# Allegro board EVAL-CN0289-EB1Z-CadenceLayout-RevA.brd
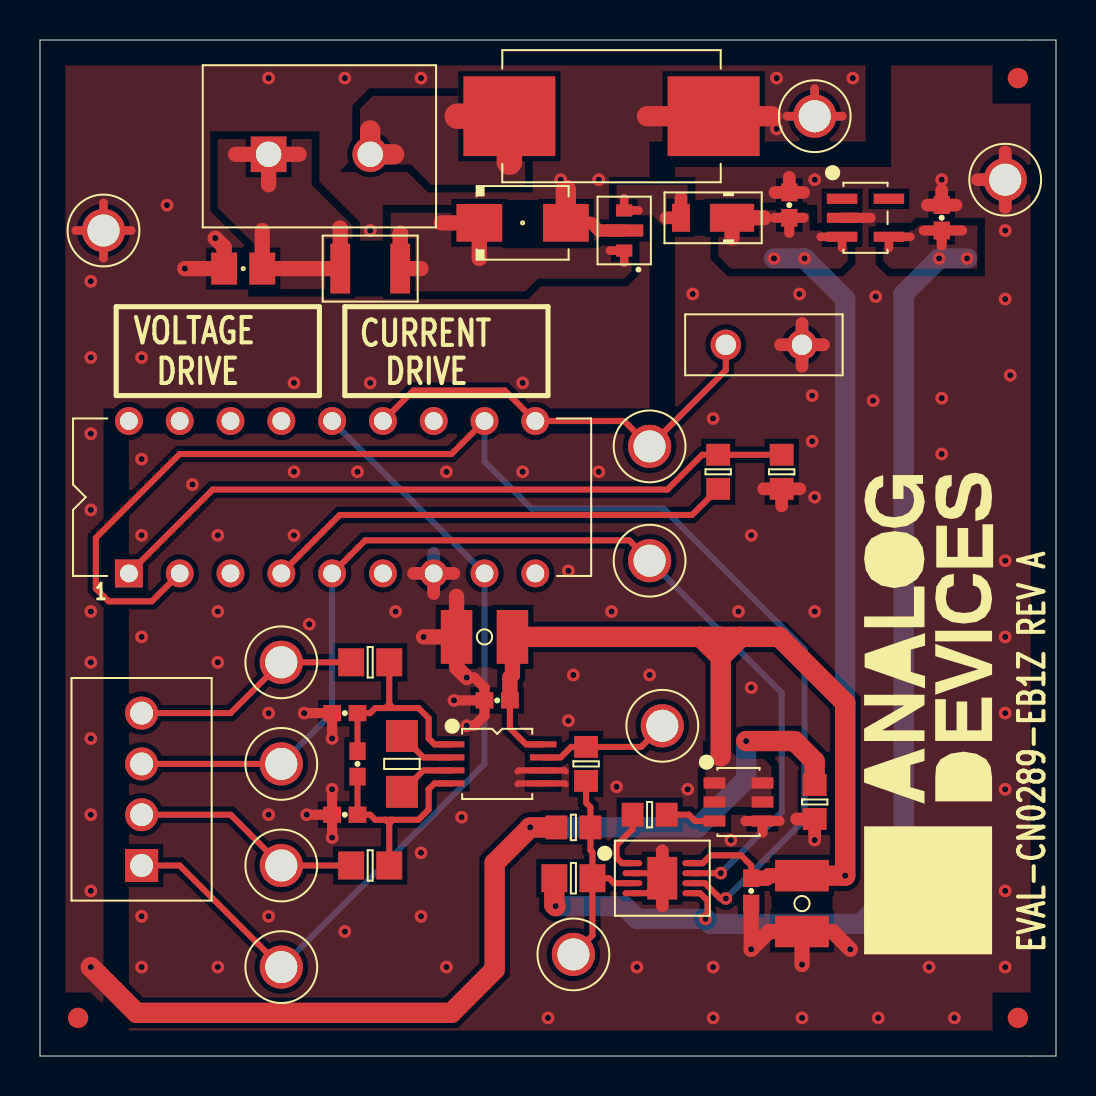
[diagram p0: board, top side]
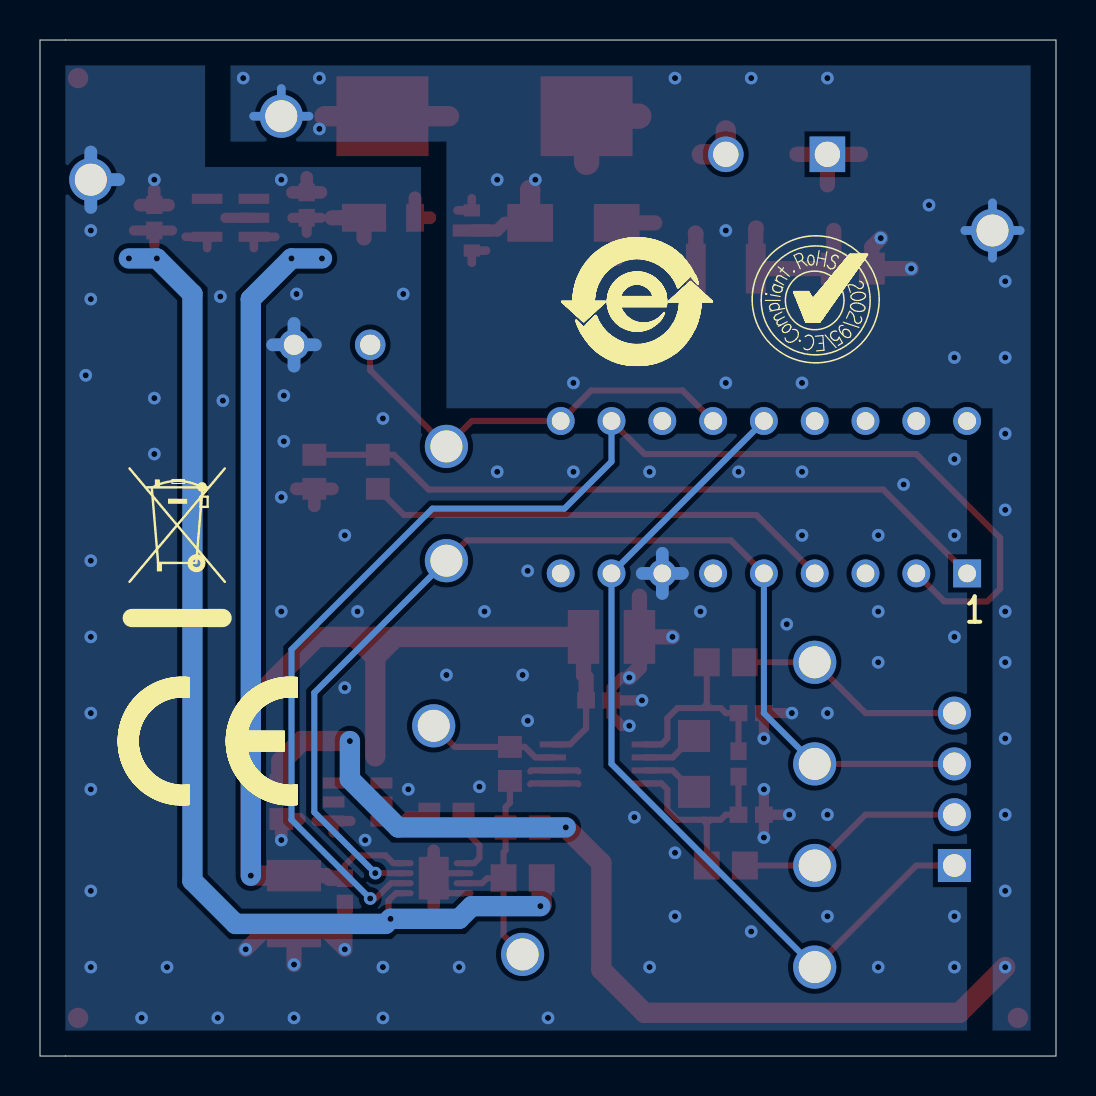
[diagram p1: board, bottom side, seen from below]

Outline 50.8 x 50.8 mm; copper layers: TOP, BOTTOM. Coordinates in mm from the lower left corner of the outline.
Outline path: 0,50.8 50.8,50.8 50.8,0 0,0 0,50.8

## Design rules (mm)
nets with their own width: min track width 0.508; nets AGND

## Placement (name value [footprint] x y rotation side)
C1  1000pF  [C0402]  15.24 17.14 180 top
C2  1000pF  [C0402]  15.24 12.06 0 top
C3  10000pF  [C0402]  15.88 14.6 270 top
C4  10uF  [C1210]  22.23 20.96 0 top
C5  1000pF  [C0402]  22.86 17.78 0 top
C6  10uF  [C1210]  38.1 7.62 90 top
C7  1000pF  [C0402]  35.56 8.25 90 top
C8  1000pF  [C0402]  37.47 42.55 270 top
C9  1000pF  [C0402]  45.09 41.91 270 top
C10  4.7UF  [C0805]  10.16 39.37 0 top
D1  SMAZ36-TP  [DIOSMJ5_0]  24.13 41.66 0 top
D2  SBR2U30P1-7  [POWERDI123]  33.66 41.91 180 top
F1  0.20A  [F1210]  16.51 39.37 0 top
FL1  0.1uF  [FSM0805L79W49H34]  29.21 41.27 90 top
GND  K24A W. EYELET T15.23  [CNLOOPTP]  48.26 43.81 0 top
GNDSNS  K24A W. EYELET T15.23  [CNLOOPTP]  12.06 4.45 0 top
J1  282834-4  [CN1X4H406]  5.08 9.53 90 top
J2  OSTTC022162  [CN1X2H406]  11.43 45.09 0 top
LOOPGND  K24A W. EYELET T15.23  [CNLOOPTP]  3.17 41.27 0 top
NOREF  -  []  -132.72 -239.08 0 top
NOREF#2  -  [unnamed#2]  1.91 1.91 0 top
NOREF#3  -  []  76.2 0 90 top
NOREF#4  -  []  1.91 1.91 0 top
NOREF#5  -  []  -30.8 140.02 0 top
NOREF#6  -  []  -15.88 -47.12 0 top
NOREF#7  -  []  0 0 0 top
NOREF#8  -  []  -132.72 -239.08 0 top
NOREF#9  -  []  0 50.8 0 top
NOREF#10  -  []  50.8 0 0 top
NOREF#11  -  []  0 50.8 0 top
NOREF#12  -  []  -132.72 -239.08 0 top
NOREF#13  -  []  0 0 0 top
NOREF#14  -  [unnamed#2]  48.9 1.91 0 top
NOREF#15  -  []  50.8 0 90 top
NOREF#16  -  []  24.64 73.91 0 top
NOREF#17  -  []  50.8 50.8 180 top
NOREF#18  -  []  1.91 1.91 0 top
NOREF#19  -  []  44.45 17.78 90 top
NOREF#20  -  []  0 0 0 top
NOREF#21  -  []  0 50.8 270 top
NOREF#22  -  [unnamed#2]  48.9 48.9 0 top
NOREF#23  -  []  12.06 37.72 180 bottom
NOREF#24  -  []  43.94 26.54 180 bottom
NOREF#25  -  []  20.96 37.72 180 bottom
NOREF#26  -  []  40.89 15.75 180 bottom
Q1  HMC313E  [SOT26-2]  34.93 12.7 270 top
R1  4.02K  [R0805]  16.51 19.69 0 top
R2  4.02K  [R0805]  16.51 9.53 0 top
R3  1K  [R1206]  18.1 14.6 90 top
R4  2.5K  [RCK02]  38.1 35.56 180 top
R5  10K  [R0603]  33.91 29.21 90 top
R6  10K  [R0603]  37.08 29.21 90 top
R7  250  [R4124]  28.58 46.99 0 top
R8  10  [R0603]  38.73 12.7 270 top
R9  30K  [R0603]  27.3 14.6 270 top
R10  1K  [R0603]  26.67 11.43 0 top
R11  30K  [R0603]  30.48 12.06 0 top
R12  130K  [R0805]  26.67 8.89 180 top
S1  ASE6204  [SWDIP18]  4.45 24.13 0 top
SUPPLYSNS  K24A W. EYELET T15.23  [CNLOOPTP]  12.06 14.6 0 top
TP1  K24A W. EYELET T15.23  [CNLOOPTP]  38.73 46.99 0 top
TP2  K24A W. EYELET T15.23  [CNLOOPTP]  30.48 24.77 0 top
TP3  K24A W. EYELET T15.23  [CNLOOPTP]  30.48 30.48 0 top
TP4  K24A W. EYELET T15.23  [CNLOOPTP]  31.12 16.51 0 top
TP5  K24A W. EYELET T15.23  [CNLOOPTP]  26.67 5.08 0 top
U1  AD8226BRMZ  [MSOP8]  22.86 14.6 270 top
U2  ADA4091-2ACPZ  [QFN8_3X3_PAD2_13X1_5]  31.12 8.89 270 top
U3  ADR02BUJZ  [TSOT-5]  41.27 41.91 270 top
UNK+V  K24A W. EYELET T15.23  [CNLOOPTP]  12.06 9.53 0 top
UNK-V  K24A W. EYELET T15.23  [CNLOOPTP]  12.06 19.69 0 top

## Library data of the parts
C1 C2 C5 C7-C9 = CAP: Tolerance: 5; User Part Number: UPN; alternate symbols: (C0402H22_ALT,C0201-2); part number: CAP_SM-1000PF,50V,5,E012419,C0402; tolerance: 5
C3 = CAP: Tolerance: 10; User Part Number: UPN; alternate symbols: (C0402H22_ALT,C0201-2); part number: CAP_SM-10000PF,25V,10,E013688,C0402; tolerance: 10
C4 C6 = CAP: Tolerance: 10; User Part Number: UPN; alternate symbols: (C0402H22_ALT,C0201-2); part number: CAP_SM-10UF,25V,10,E011786,C1210; tolerance: 10
C10 = CAP: Tolerance: 10; User Part Number: UPN; alternate symbols: (C0402H22_ALT,C0201-2); part number: CAP_SM-4.7UF,25V,10,E006908,C0805; tolerance: 10
D1 = DIOZNR: Tolerance: 5; User Part Number: UPN; part number: DIOZNR_SM-SMAZ36-TP,36V,5,E017811,DIOSMJ5_0; tolerance: 5
D2 = DIO: User Part Number: UPN; Tolerance: N/A; part number: DIO_SM-SBR2U30P1-7,30V,N/A,E016912,POWERDI123; tolerance: N/A
F1 = FSFUSE: User Part Number: UPN; part number: FSFUSE_SM-0.20A,30V,E016947,F1210
FL1 = FLTR3P: Tolerance: 20; User Part Number: UPN; part number: FLTR3P_SM-0.1UF,E010964,FSM0805L79W49H34; tolerance: 20
GND GNDSNS LOOPGND SUPPLYSNS TP1-TP5 UNK+V UNK-V = CNTP1P: User Part Number: UPN; part number: CNTP1P_TH-K24A W. EYELET T15.23,E005673,CNLOOPTP
J1 = CN4P: User Part Number: UPN; part number: CN4P_TH-282834-4,E016935,CN1X4H406
J2 = CN2P: User Part Number: UPN; part number: CN2P_TH-OSTTC022162,E016936,CN1X2H406
Q1 = ICHMC313: User Part Number: UPN; part number: ICHMC313_SM-HMC313E,E010134,SOT26-2
R1 R2 = RES: Tolerance: 1; User Part Number: UPN; alternate symbols: (RRAD984L1500W75H520LD32); part number: RES_SM-4.02K,1/8W,1,E003522,R0805; tolerance: 1
R3 = RES: Tolerance: 0.05; User Part Number: UPN; alternate symbols: (RRAD984L1500W75H520LD32); part number: RES_SM-1K,1/4W,0.05,E004440,R1206; tolerance: 0.05
R4 = RES: Tolerance: 0.005; User Part Number: UPN; alternate symbols: (RRAD984L1500W75H520LD32;TO220H590_ALT); part number: RES_TH-2.5K,0.6W,0.005,E017769,RCK02; tolerance: 0.005
R5 R6 = RES: Tolerance: 1; User Part Number: UPN; alternate symbols: (RRAD984L1500W75H520LD32); part number: RES_SM-10K,1/10W,1,E003671,R0603; tolerance: 1
R7 = RES: Tolerance: 1; User Part Number: UPN; alternate symbols: (RRAD984L1500W75H520LD32); part number: RES_SM-250,2W,1,E017807,R4124; tolerance: 1
R8 = RES: Tolerance: 1; User Part Number: UPN; alternate symbols: (RRAD984L1500W75H520LD32); part number: RES_SM-10,1/10W,1,E003666,R0603; tolerance: 1
R9 R11 = RES: Tolerance: 0.1; User Part Number: UPN; alternate symbols: (RRAD984L1500W75H520LD32); part number: RES_SM-30K,1/10W,0.1,E003958,R0603; tolerance: 0.1
R10 = RES: Tolerance: 0.1; User Part Number: UPN; alternate symbols: (RRAD984L1500W75H520LD32); part number: RES_SM-1K,1/10W,0.1,E010662,R0603; tolerance: 0.1
R12 = RES: Tolerance: 1; User Part Number: UPN; alternate symbols: (RRAD984L1500W75H520LD32); part number: RES_SM-130K,1/8W,1,E003566,R0805; tolerance: 1
S1 = SW6PDT: User Part Number: UPN; part number: SW6PDT_TH-ASE6204,E016934,SWDIP18
U1 = AD8220: User Part Number: UPN; part number: AD8220_SM-AD8226BRMZ,E013818,MSOP8,N/A
U2 = ADA4091_2: User Part Number: UPN; part number: ADA4091_2_SM-ADA4091-2ACPZ,E016852,QFN8_3X3_PAD2_13X1_5,N/A
U3 = ADR0X: User Part Number: UPN; part number: ADR0X_SM-ADR02BUJZ,E016933,TSOT-5,N/A

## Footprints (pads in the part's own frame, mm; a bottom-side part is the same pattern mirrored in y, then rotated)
C0402
  rect 0.889x0.813 smd: 1(-0.635,0) 2(0.635,0)
C0805
  rect 1.295x1.6 smd: 1(-0.953,0) 2(0.953,0)
C1210
  rect 1.575x2.692 smd: 1(-1.397,0) 2(1.397,0)
CN1X2H406
  rect 1.778x1.778 hole 1.27: 1(0,0)
  round 1.778 hole 1.27: 2(5.08,0)
CN1X4H406
  rect 1.651x1.651 hole 1.143: 1(0,0)
  round 1.651 hole 1.143: 2(2.54,0) 3(5.08,0) 4(7.62,0)
CNLOOPTP
  round 2.159 hole 1.6: 1(0,0)
DIOSMJ5_0
  rect 2.286x1.88 smd: A(2.164,0) C(-2.164,0)
F1210
  rect 0.991x2.489 smd: 1(-1.499,0) 2(1.499,0)
FSM0805L79W49H34
  rect 0.61x0.813 smd: 1(-1.005,0) 3(1.005,0)
  rect 0.61x1.905 smd: 2(0,0)
MSOP8
  rect 0.305x1.321 smd: 1(-0.975,-2.3) 2(-0.325,-2.3) 3(0.325,-2.3) 4(0.975,-2.3) 5(0.975,2.3) 6(0.325,2.3) 7(-0.325,2.3) 8(-0.975,2.3)
POWERDI123
  rect 0.889x1.397 smd: A(1.606,0)
  rect 2.21x1.397 smd: C(-0.945,0)
QFN8_3X3_PAD2_13X1_5
  oval 0.305x0.991 smd: 1(-0.75,-1.495) 2(-0.25,-1.495) 3(0.25,-1.495) 4(0.75,-1.495) 5(0.75,1.495) 6(0.25,1.495) 7(-0.25,1.495) 8(-0.75,1.495)
  rect 2.134x1.499 smd: PAD(0,0)
R0603
  rect 1.092x1.194 smd: 1(-0.851,0) 2(0.851,0)
R0805
  rect 1.295x1.397 smd: 1(-0.953,0) 2(0.953,0)
R1206
  rect 1.6x1.6 smd: 1(-1.397,0) 2(1.397,0)
R4124
  rect 4.597x3.988 smd: 1(-5.105,0) 2(5.105,0)
RCK02
  round 1.524 hole 1.016: 1(0,0) 2(3.81,0)
SOT26-2
  rect 0.559x1.092 smd: 1(-0.95,-1.2) 2(0,-1.2) 3(0.95,-1.2) 4(0.95,1.2) 5(0,1.2) 6(-0.95,1.2)
SWDIP18
  rect 1.397x1.397 hole 0.889: 1(0,0)
  round 1.397 hole 0.889: 2(2.54,0) 3(5.08,0) 4(7.62,0) 5(10.16,0) 6(12.7,0) 7(15.24,0) 8(17.78,0) 9(20.32,0) 10(20.32,7.62) 11(17.78,7.62) 12(15.24,7.62) 13(12.7,7.62) 14(10.16,7.62) 15(7.62,7.62) 16(5.08,7.62) 17(2.54,7.62) 18(0,7.62)
TSOT-5
  rect 0.508x1.524 smd: 1(-0.95,-1.17) 2(0,-1.17) 3(0.95,-1.17) 4(0.95,1.17) 5(-0.95,1.17)
unnamed#2
  round 1.016 smd: (0,0)

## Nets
+5V: C9.2(N2) R12.2(N2) U2.5(+IN) U3.4(VOUT)
+VCC: C4.2(N2) C5.2(N2) C6.2(N2) C7.2(N2) C8.2(N2) D2.C(N) Q1.1(OUT) Q1.2(GND2) Q1.5(GND5) Q1.6(GND6) U1.8(VS+) U2.8(+V) U3.3(VIN)
AGND: C1.2(N2) C2.1(N1) C4.1(N1) C5.1(N1) C6.1(N1) C7.1(N1) C8.1(N1) C9.1(N1) GND.1(N1) Q1.4(GND4) R4.1(N1) R6.1(N1) R8.2(N2) S1.7(NC3) U1.5(VS-) U1.6(REF) U2.2(-IN) U2.4(-V) U2.PAD(-V1) U3.2(GND)
DGND: C10.1(N1) D1.A(P) FL1.2(GND) LOOPGND.1(N1) R7.2(N2) R8.1(N1) R10.1(N1) TP1.1(N1)
+V_SENSOR_OUTPUT: J1.2(N2) R2.1(N1) UNK+V.1
-V_SENSOR_OUTPUT: J1.4(N4) R1.1(N1) UNK-V.1
OUTA: R11.1(N1) U2.1(OUT)
SENSOR_GND: GNDSNS.1(N1) J1.1(N1) S1.8(C3) S1.14(C5)
SENSOR_SUPPLY: J1.3(N3) S1.5(C2) SUPPLYSNS.1(N1) TP2.1(N1) U2.7(OUT)
UNNAMED_2_AD8220_I94_IN: C1.1(N1) C3.1(N1) R1.2(N2) U1.1(IN-)
UNNAMED_2_AD8220_I94_IN_1: C2.2(N2) C3.2(N2) R2.2(N2) U1.4(IN+)
UNNAMED_2_AD8220_I94_OUT: R9.1(N1) TP4.1(N1) U1.7(OUT)
UNNAMED_2_AD8220_I94_RG: R3.2(N2) U1.2(RG)
UNNAMED_2_AD8220_I94_RG1: R3.1(N1) U1.3(RG1)
UNNAMED_2_ADA40912_I91__1: R9.2(N2) R10.2(N2) R12.1(N1) TP5.1(N1) U2.3(+IN)
UNNAMED_2_ADA40912_I92_: S1.2(C1) S1.11(C4) U2.6(-IN)
UNNAMED_2_CAP_I98_N2: C10.2(N2) F1.1(N1) J2.1(N1)
UNNAMED_2_CN2P_I187_N2: J2.2(N2) R7.1(N1)
UNNAMED_2_CNTP1P_I152_N1: R4.2(N2) S1.10(NO4) S1.13(NO5) TP3.1(N1)
UNNAMED_2_DIO_I100_P: D2.A(P) FL1.3(OUT)
UNNAMED_2_FLTR3P_I123_IN: D1.C(N) F1.2(N2) FL1.1(IN)
UNNAMED_2_RES_I113_N1: R5.1(N1) S1.4(NC2)
UNNAMED_2_RES_I113_N2: R5.2(N2) R6.2(N2) S1.1(NC1)
UNNAMED_2_RES_I159_N2: Q1.3(IN) R11.2(N2)

Pads without a net: S1 3 6 9 12 15 16 17 18; U3 1 5

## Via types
v1: diameter 0.635, hole 0.305, TOP to BOTTOM, 117 vias

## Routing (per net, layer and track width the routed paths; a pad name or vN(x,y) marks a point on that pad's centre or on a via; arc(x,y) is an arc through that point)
+5V: length 59.5
  TOP w0.305: v1(33.27,6.86) 33.38,6.96 33.38,7.77 33.01,8.14 U2.5
  TOP w0.432: 42.44,40.4 U3.4 43.51,40.96
  TOP w0.508: 46.1,41.27 C9.2 ; C9.2 45.09,40.53 ; C9.2 44.2,41.27
  TOP w1.016: R12.2 25.72,7.56 v1(25.78,7.49)
  BOTTOM w1.016: v1(25.78,7.49) 29.21,7.49 29.85,6.86 v1(33.27,6.86) 33.53,6.6 41.02,6.6 43.18,8.76 43.18,38.1 v1(44.96,39.88) v1(46.36,39.88)
+VCC: length 90.4
  TOP w0.305: C7.2 35.56,9.53 35.05,10.03 33.53,10.03 33.14,9.64 U2.8 ; U1.8 24.3,15.58 23.5,16.38 C5.2
  TOP w0.432: 40.11,40.4 U3.3 39.04,40.96
  TOP w0.508: C8.2 36.75,41.91 ; C8.2 37.47,41.16 ; C8.2 38.18,41.91
  TOP w0.762: C7.2 36.32,8.89 36.45,9.02 C6.2 ; 36.2,41.91 D2.C 34.6,40.91 ; C4.2 23.62,19.05 23.5,18.92 C5.2
  TOP w1.016: 34.04,19.94 35.05,20.96 ; 34.04,19.94 34.04,20.96 ; 34.04,19.94 34.04,14.99 ; 34.04,19.94 33.02,20.96 ; 35.05,20.96 36.96,20.96 40.26,17.65 v1(40.26,9.02) C6.2 ; 35.05,20.96 34.04,20.96 ; 34.04,20.96 33.02,20.96 ; 33.02,20.96 C4.2
  BOTTOM w1.016: v1(36.7,39.88) v1(38.23,39.88) 40.26,37.85 v1(40.26,9.02)
AGND: length 74.4
  TOP w0.305: 26.29,14.22 26.23,14.28 U1.6 23.93,14.28 23.88,14.22 ; 23.88,13.59 23.92,13.63 U1.5 26.25,13.63 26.29,13.59 ; U2.2 30.87,9.14 U2.PAD 30.36,8.14 U2.4
  TOP w0.508: C5.1 22.23,17.02 21.72,16.51 v1(21.34,16.51) ; C5.1 v1(20.7,17.78) ; C5.1 22.23,18.42 21.72,18.92 v1(21.34,18.92) ; C2.1 v1(14.6,13.33) ; C2.1 v1(13.33,12.06) ; C2.1 v1(14.6,10.92) ; v1(13.21,17.14) C1.2 v1(14.6,15.88) ; 36.12,11.17 Q1.4 ; Q1.4 35.27,11.75 ; Q1.4 36.98,11.75 ; U3.2 41.53,41.91
  TOP w0.635: S1.7 20.69,24.13 ; S1.7 19.69,23.13 ; S1.7 18.68,24.13 ; GND.1 48.26,45.2 ; GND.1 46.88,43.81 ; GND.1 48.26,42.43 ; 31.12,7.52 U2.PAD 31.12,10.26 ; C9.1 45.09,43.29 ; C9.1 44.37,42.55 ; C9.1 45.8,42.55 ; R4.1 39.17,35.56 ; R4.1 38.1,34.49 ; R4.1 37.03,35.56 ; R4.1 38.1,36.63 ; 36.18,28.36 R6.1 ; R6.1 37.99,28.36 ; R6.1 37.08,27.51 ; C8.1 38.18,43.18 ; C8.1 37.47,43.93 ; C8.1 36.75,43.18 ; 38.73,11 R8.2 37.83,11.85
  TOP w0.762: C4.1 20.83,22.99 ; C4.1 v1(19.18,20.96) ; C4.1 20.83,19.43 v1(21.34,18.92) ; C7.1 v1(35.56,5.33) 36.45,6.22 C6.1 ; C6.1 39.62,6.22 v1(40.51,5.33) ; C6.1 v1(38.1,4.57)
  BOTTOM w0.635: 37.03,35.56 R4.1 ; R4.1 38.1,36.63 ; R4.1 38.1,34.49 ; R4.1 39.17,35.56 ; 18.68,24.13 S1.7 ; S1.7 20.69,24.13 ; S1.7 19.69,25.13 ; S1.7 19.69,23.13 ; 46.88,43.81 GND.1 ; GND.1 48.26,45.2 ; GND.1 48.26,42.43
  vias: v1(5.08,29.85) v1(5.08,26.04) v1(5.08,20.96) v1(5.08,6.99) v1(5.08,4.45) v1(7.62,28.58) v1(8.89,26.04) v1(8.89,22.23) v1(8.89,19.69) v1(8.89,4.45) v1(11.43,17.14) v1(11.43,12.06) v1(11.43,6.99) v1(12.7,29.21) v1(12.7,26.04) v1(13.46,21.59) v1(15.24,6.22) v1(15.88,29.21) v1(17.78,22.23) v1(19.05,10.16) v1(19.05,6.99) v1(20.32,29.21) v1(20.32,4.45) v1(21.08,11.94) v1(24.13,29.21) v1(25.4,1.91) v1(26.42,24.26) v1(26.42,16.76) v1(26.67,19.05) v1(27.94,29.21) v1(28.58,22.23) v1(28.83,13.46) v1(29.85,4.45) v1(30.48,19.05) v1(32.38,13.33) v1(32.64,38.1) v1(33.66,31.88) v1(33.66,4.45) v1(33.66,1.91) v1(34.54,10.79) v1(34.93,22.23) v1(35.56,26.04) v1(35.56,18.42) v1(37.97,38.1) v1(38.1,1.91) v1(38.61,33.02) v1(38.61,30.73) v1(38.73,43.81) v1(38.73,27.94) v1(38.73,22.23) v1(38.73,10.79) v1(41.66,32.77) v1(41.78,37.97) v1(41.91,1.91) v1(44.45,4.45) v1(45.09,43.81) v1(45.09,32.89) v1(45.09,30.1) v1(45.72,1.91) v1(48.26,41.27) v1(48.26,37.85) v1(48.26,24.77) v1(48.26,20.96) v1(48.26,17.14) v1(48.26,13.33) v1(48.26,8.25) v1(48.26,4.45) v1(48.51,34.04)
DGND: length 83.9
  TOP w0.432: LOOPGND.1 4.56,41.27 ; LOOPGND.1 3.17,42.66 ; LOOPGND.1 1.79,41.27 ; LOOPGND.1 3.17,39.89 ; TP1.1 38.73,48.37 ; TP1.1 37.35,46.99 ; TP1.1 40.12,46.99
  TOP w0.61: FL1.2 27.94,41.27 27.56,41.66 D1.A
  TOP w0.762: v1(7.24,39.37) C10.1 9.21,40.45 v1(8.76,40.89)
  TOP w1.016: 36.58,46.99 R7.2 30.35,46.99 ; v1(35.31,15.75) 37.72,15.75 38.73,14.73 R8.1 ; D1.A 26.29,43.3 26.29,43.31 ; R10.1 v1(24.51,11.43) 22.73,9.65 22.73,4.32 20.57,2.16 4.83,2.16 v1(2.54,4.45)
  BOTTOM w0.432: TP1.1 40.12,46.99 ; TP1.1 37.35,46.99 ; TP1.1 38.73,48.37 ; LOOPGND.1 3.17,42.66 ; LOOPGND.1 4.56,41.27 ; LOOPGND.1 1.79,41.27 ; LOOPGND.1 3.17,39.89
  BOTTOM w1.016: v1(24.51,11.43) 32.89,11.43 35.31,13.84 v1(35.31,15.75)
  vias: v1(2.54,38.73) v1(2.54,34.93) v1(2.54,31.12) v1(2.54,27.3) v1(2.54,22.23) v1(2.54,19.69) v1(2.54,15.88) v1(2.54,12.06) v1(2.54,8.25) v1(5.08,34.93) v1(6.35,42.55) v1(11.43,48.9) v1(12.7,33.66) v1(15.24,48.9) v1(16.51,41.27) v1(16.51,33.66) v1(19.05,48.9) v1(24.13,33.66) v1(26.04,43.81) v1(27.94,43.81) v1(36.83,48.9) v1(36.83,46.36) v1(40.64,48.9)
+V_SENSOR_OUTPUT: length 11.5
  TOP w0.305: J1.2 9.53,12.06 UNK+V.1 R2.1
-V_SENSOR_OUTPUT: length 11.5
  TOP w0.305: R1.1 UNK-V.1 9.53,17.14 J1.4
OUTA: length 3.4
  TOP w0.305: U2.1 29.09,9.64 28.83,9.91 28.83,10.54 29.63,11.34 R11.1
SENSOR_GND: length 43.8
  TOP w0.305: J1.1 6.99,9.53 GNDSNS.1
  BOTTOM w0.305: GNDSNS.1 22.23,14.6 S1.8 14.6,31.75
SENSOR_SUPPLY: length 55.6
  TOP w0.305: S1.5 16.26,25.78 29.46,25.78 TP2.1 ; U2.7 34.03,9.14 v1(34.04,9.14) ; J1.3 SUPPLYSNS.1
  BOTTOM w0.305: TP2.1 37.08,18.16 37.08,12.19 v1(34.04,9.14) ; SUPPLYSNS.1 14.6,17.14 S1.5
UNNAMED_2_AD8220_I94_IN: length 10.9
  TOP w0.305: 17.65,17.4 18.92,17.4 19.43,16.89 19.43,15.88 19.73,15.58 U1.1 ; 17.65,17.4 17.46,17.59 ; 17.65,17.4 17.53,17.4 ; 17.46,17.59 R1.2 ; 17.46,17.59 17.27,17.4 ; 17.46,17.59 17.46,17.46 17.53,17.4 ; 17.27,17.4 17.53,17.4 ; 17.27,17.4 16.76,17.4 16.51,17.14 C1.1 15.88,15.24
UNNAMED_2_AD8220_I94_IN_1: length 10.9
  TOP w0.305: 17.46,11.62 17.27,11.81 ; 17.46,11.62 R2.2 ; 17.46,11.62 17.46,11.75 17.53,11.81 ; 17.46,11.62 17.65,11.81 ; 17.27,11.81 17.53,11.81 ; 17.27,11.81 16.76,11.81 16.51,12.06 C2.2 C3.2 ; 17.53,11.81 17.65,11.81 ; U1.4 19.73,13.63 19.43,13.33 19.43,12.32 18.92,11.81 17.65,11.81
UNNAMED_2_AD8220_I94_OUT: length 6.6
  TOP w0.305: TP4.1 30.06,15.46 R9.1 26.56,15.46 26.04,14.93 U1.7
UNNAMED_2_AD8220_I94_RG: length 2.9
  TOP w0.305: U1.2 19.17,14.93 R3.2
UNNAMED_2_AD8220_I94_RG1: length 2.9
  TOP w0.305: 18.1,13.21 19.17,14.28 U1.3
UNNAMED_2_ADA40912_I91__1: length 11.3
  TOP w0.305: R12.1 28.45,8.89 28.7,8.64 U2.3 ; R12.1 27.62,6.03 TP5.1 ; R12.1 27.62,10.19 27.52,10.29 R10.2 27.52,12.45 27.3,12.66 R9.2
UNNAMED_2_ADA40912_I92_: length 67.4
  TOP w0.305: 22.23,31.75 20.57,30.1 6.99,30.1 2.79,25.91 2.79,23.37 3.43,22.73 5.59,22.73 S1.2 ; v1(34.29,7.87) 34.01,7.87 33.25,8.64 U2.6
  BOTTOM w0.305: 22.23,31.75 22.23,29.72 24.57,27.37 31.18,27.37 38.23,20.32 38.23,11.81 v1(34.29,7.87)
UNNAMED_2_CAP_I98_N2: length 12.5
  TOP w0.762: 9.78,45.09 J2.1 ; J2.1 12.95,45.09 ; J2.1 11.43,43.56 ; 11.11,41.27 C10.2 F1.1 15.01,41.38 14.99,41.4
UNNAMED_2_CN2P_I187_N2: length 7.3
  TOP w1.016: 17.7,45.09 J2.2 16.51,46.28
  TOP w1.27: 20.87,46.99 R7.1 23.47,44.69
UNNAMED_2_CNTP1P_I152_N1: length 21.8
  TOP w0.305: 17.14,31.75 18.67,33.27 23.24,33.27 24.77,31.75 29.21,31.75 TP3.1 34.29,34.29 R4.2
UNNAMED_2_DIO_I100_P: length 3.1
  TOP w0.432: 29.92,42.28 FL1.3 29.21,42.89
  TOP w0.635: 31.3,41.91 D2.A 32.05,42.91
UNNAMED_2_FLTR3P_I123_IN: length 7.8
  TOP w0.432: 29.21,39.66 FL1.1 28.5,40.27
  TOP w0.762: 21.97,39.88 21.97,39.88 D1.C 20.07,41.66 ; 18.03,41.15 18.01,41.12 F1.2 19.05,39.37
UNNAMED_2_RES_I113_N1: length 23.6
  TOP w0.305: S1.4 14.99,27.05 32.6,27.05 R5.1
UNNAMED_2_RES_I113_N2: length 35.1
  TOP w0.305: S1.1 8.64,28.32 31.37,28.32 33.11,30.06 R5.2 R6.2
UNNAMED_2_RES_I159_N2: length 2.5
  TOP w0.305: Q1.3 32.77,11.75 32.45,12.06 R11.2

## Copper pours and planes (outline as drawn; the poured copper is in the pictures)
+5V on TOP: 42.55,39.37 42.16,39.75 42.16,41.27 43.69,41.27 43.94,41.53 46.86,41.53 46.86,39.37
+VCC on TOP: 34.54,39.37 33.91,40.01 33.91,42.29 37.97,42.29 37.97,42.16 38.48,42.16 38.48,41.27 40.39,41.27 40.39,39.75 40.01,39.37
+VCC on TOP: 33.27,12.45 36.58,12.45 36.58,14.48 36.2,14.86 34.93,14.86 34.42,15.37 33.53,15.37 33.53,14.48 33.27,14.22
AGND on TOP: 4.45,1.27 4.45,31.12 31.75,31.12 31.75,44.45 42.55,44.45 42.55,49.53 47.62,49.53 47.62,47.62 49.53,47.62 49.53,3.17 47.62,3.17 47.62,1.27 ; 7 cut-outs
AGND on BOTTOM: 4.45,1.27 4.45,31.12 31.75,31.12 31.75,44.45 42.55,44.45 42.55,49.53 49.53,49.53 49.53,1.27
DGND on TOP: 3.17,2.54 2.54,3.17 1.27,3.17 1.27,49.53 30.48,49.53 41.27,49.53 41.27,45.72 30.48,45.72 30.48,32.38 3.17,32.38 ; 3 cut-outs
DGND on BOTTOM: 1.27,3.17 1.27,49.53 30.48,49.53 41.27,49.53 41.27,45.72 30.48,45.72 30.48,32.38 3.17,32.38 3.17,1.27 1.27,1.27 1.27,3.17
UNNAMED_2_CAP_I98_N2 on TOP: 8.89,45.85 13.59,45.85 13.59,43.56 15.62,41.53 15.62,38.35 10.79,38.35 10.79,40.51 8.89,42.42
UNNAMED_2_CN2P_I187_N2 on TOP: 15.88,44.58 18.54,44.58 19.56,43.56 24.26,43.56 24.26,48.01 16.64,48.01 16,47.37 16,44.7
UNNAMED_2_DIO_I100_P on TOP: 31.12,41.53 30.61,42.04 28.83,42.04 28.83,43.56 32.38,43.56 32.38,41.53
UNNAMED_2_FLTR3P_I123_IN on TOP: 17.53,38.23 17.53,42.16 23.11,42.16 23.11,40.39 27.94,40.39 28.07,40.51 29.59,40.51 29.59,39.24 29.21,38.86 24.89,38.86 24.26,38.23

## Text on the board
Ref Des/Silkscreen Top: VOLTAGE | DRIVE | CURRENT | EVAL-CN0289-EB1Z REV A
DIMENSION: REF
PAGE_OUTLINE: N/A | 24JUL12 | 10JAN13 | AD8226/ADA4091 CUSTOMER | EVALUATION BOARD | 20-035415
User.5: ROHS COMPLIANCE NOTE:  (Required for Customer Boards) Add to top of MATERIALS | 100 MICRO INCHES NICKEL/ | 3-5 MICRO INCHES GOLD | HOMOGENOUS MATERIALS IN THIS BOARD SHALL BE COMPLIANT | THE EU RoHS DIRECTIVE 2002/95/EC
User.8: 08-      -01 | LAYER1 PRIMARY SIDE
User.9: 08-      -02 | LAYER2 SECONDARY SIDE
User.11: 08-      -07 | LAYER2_AGND
User.12: 08-      -08 | LAYER3_DGND
User.14: SECONDARY SIDE PASTEMASK | 08-      -12
User.27: 20-035415
User.33: FIGURE | SIZE | 12.0 | 35.0 | 40.0 | 45.0 | 50.0 | 63.0 | DRILL CHART: TOP to BOTTOM | ALL UNITS ARE IN MILS | TOLERANCE | +3.0/-3.0 | PLATED | QTY | 117 | 18 | 2 | 3 | 1 | 11
